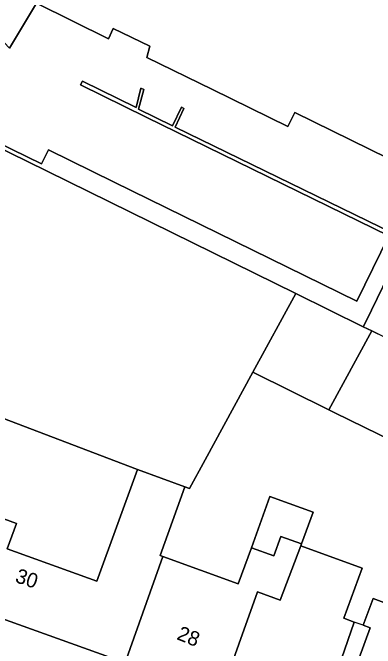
# Model space of a CAD drawing. Extents: x 160023 to 161302, y 384750 to 385707.
# Drawn here: x 160652.2 to 160677, y 385250.71 to 385294.19 of the extents above; entities that cross this region are included whole.
import ezdxf

# ---------------------------------------------------------------- set-up
doc = ezdxf.new("R2010")
doc.units = 0
for name, color, linetype in [('IMGEO_Erf', 7, 'Continuous'), ('IMGEO_Muur', 7, 'Continuous'), ('IMGEO_Pand', 7, 'Continuous'), ('IMGEO_Pand_nummerreeks', 7, 'Continuous'), ('IMGEO_Pand_overbouw', 7, 'Continuous'), ('IMGEO_Voetpad_open', 7, 'Continuous')]:
    doc.layers.add(name, color=color, linetype=linetype)

msp = doc.modelspace()

# ---------------------------------------------------------------- linework, layer by layer
at = {"layer": 'IMGEO_Erf'}
for points in [[(160689.378, 385278.591), (160671.488, 385287.366), (160671.014, 385286.405), (160665.855, 385288.934), (160661.365, 385291.134), (160661.571, 385291.91), (160659.07, 385293.109), (160658.75, 385292.417), (160653.825, 385294.836), (160651.991, 385291.772)], [(160649.069, 385286.341), (160654.173, 385283.853), (160654.654, 385284.802), (160659.144, 385282.6), (160675.733, 385274.462), (160677.927, 385278.94), (160661.328, 385287.057), (160656.836, 385289.253), (160656.984, 385289.518), (160660.638, 385287.701), (160660.971, 385289.036), (160661.179, 385288.947), (160660.815, 385287.596), (160663.133, 385286.456), (160663.734, 385287.727), (160663.915, 385287.639), (160663.312, 385286.373), (160679.084, 385278.668), (160676.343, 385273.047), (160676.178, 385272.71), (160676.768, 385272.42), (160677.177, 385272.22)], [(160680.258, 385263.867), (160674.239, 385266.827), (160673.831, 385267.028), (160668.622, 385269.591), (160665.364, 385263.611), (160664.293, 385261.646), (160663.97, 385261.763), (160662.283, 385257.055), (160662.474, 385256.986), (160667.621, 385255.114), (160668.522, 385257.591), (160669.796, 385261.095), (160671.111, 385260.617), (160672.746, 385260.023), (160671.956, 385257.849), (160671.906, 385257.713), (160676.097, 385256.189), (160674.851, 385252.763), (160675.556, 385252.507), (160674.688, 385250)], [(160675.885, 385250), (160676.645, 385252.112), (160676.169, 385252.285), (160676.853, 385254.114), (160677.592, 385253.837)]]:
    msp.add_lwpolyline(points, dxfattribs=at)
msp.add_lwpolyline([(160660.727, 385262.941), (160650.478, 385266.833), (160649.617, 385264.465), (160650.379, 385264.188), (160649.038, 385260.498), (160652.456, 385259.256), (160651.826, 385257.523), (160657.949, 385255.297)], close=True, dxfattribs=at)
at = {"layer": 'IMGEO_Muur'}
msp.add_lwpolyline([(160679.084, 385278.668), (160663.312, 385286.373), (160663.915, 385287.639), (160663.734, 385287.727), (160663.133, 385286.456), (160660.815, 385287.596), (160661.179, 385288.947), (160660.971, 385289.036), (160660.638, 385287.701), (160656.984, 385289.518), (160656.836, 385289.253), (160661.328, 385287.057), (160677.927, 385278.94), (160675.733, 385274.462), (160659.144, 385282.6), (160654.654, 385284.802), (160654.173, 385283.853), (160649.069, 385286.341), (160648.914, 385286.122), (160653.165, 385284.031), (160671.559, 385274.983), (160676.178, 385272.71), (160676.343, 385273.047)], close=True, dxfattribs=at)
at = {"layer": 'IMGEO_Pand'}
for points in [[(160653.825, 385294.836), (160658.75, 385292.417), (160659.07, 385293.109), (160661.571, 385291.91), (160661.365, 385291.134), (160665.855, 385288.934), (160671.014, 385286.405), (160671.488, 385287.366), (160689.378, 385278.591)], [(160659.974, 385250), (160662.474, 385256.986), (160662.283, 385257.055), (160663.97, 385261.763), (160660.727, 385262.941), (160657.949, 385255.297), (160651.826, 385257.523), (160652.456, 385259.256), (160649.038, 385260.498), (160650.379, 385264.188), (160649.617, 385264.465), (160650.478, 385266.833), (160648.891, 385267.409), (160644.833, 385269.176), (160643.748, 385266.188), (160639.654, 385267.675), (160639.265, 385266.604), (160638.538, 385266.264), (160637.856, 385264.388), (160638.238, 385263.57), (160636.978, 385260.104), (160645.265, 385257.093), (160644.582, 385255.212), (160659.142, 385250)]]:
    msp.add_lwpolyline(points, dxfattribs=at)
for points in [[(160671.559, 385274.983), (160653.165, 385284.031), (160648.914, 385286.122), (160648.678, 385286.238), (160642.926, 385274.57), (160643.169, 385274.482), (160643.026, 385274.089), (160641.66, 385274.22), (160640.663, 385271.476), (160644.833, 385269.176), (160648.891, 385267.409), (160650.478, 385266.833), (160660.727, 385262.941), (160663.97, 385261.763), (160664.293, 385261.646), (160665.364, 385263.611), (160668.622, 385269.591)], [(160676.768, 385272.42), (160676.178, 385272.71), (160671.559, 385274.983), (160668.622, 385269.591), (160673.831, 385267.028)], [(160682.966, 385269.372), (160677.177, 385272.22), (160676.768, 385272.42), (160673.831, 385267.028), (160674.239, 385266.827), (160680.258, 385263.867), (160681.775, 385266.95)], [(160668.522, 385257.591), (160670.061, 385257.04), (160670.533, 385258.359), (160671.956, 385257.849), (160672.746, 385260.023), (160671.111, 385260.617), (160669.796, 385261.095)], [(160668.947, 385254.571), (160670.497, 385254.002), (160671.906, 385257.713), (160671.956, 385257.849), (160670.533, 385258.359), (160670.061, 385257.04), (160668.522, 385257.591), (160667.621, 385255.114), (160662.474, 385256.986), (160659.974, 385250), (160659.879, 385249.736), (160666.383, 385247.408)], [(160675.556, 385252.507), (160674.851, 385252.763), (160676.097, 385256.189), (160671.906, 385257.713), (160670.497, 385254.002), (160668.947, 385254.571), (160666.383, 385247.408), (160672.971, 385245.05), (160674.61, 385249.774), (160674.688, 385250)], [(160683.182, 385249.434), (160681.881, 385250), (160683.086, 385253.559), (160683.224, 385253.966), (160678.326, 385255.798), (160677.592, 385253.837), (160676.853, 385254.114), (160676.169, 385252.285), (160676.645, 385252.112), (160675.885, 385250), (160675.666, 385249.391), (160673.97, 385244.687), (160680.582, 385242.281)]]:
    msp.add_lwpolyline(points, close=True, dxfattribs=at)
at = {"layer": 'IMGEO_Pand_overbouw'}
msp.add_lwpolyline([(160675.556, 385252.507), (160674.688, 385250), (160674.61, 385249.774), (160672.971, 385245.05), (160673.97, 385244.687), (160676.645, 385252.112), (160676.169, 385252.285)], close=True, dxfattribs=at)
at = {"layer": 'IMGEO_Voetpad_open'}
for points in [[(160667.487, 385318.357), (160664.42, 385318.987), (160661.219, 385313.176), (160658.126, 385308.018), (160649.267, 385294.611), (160651.991, 385291.772), (160653.825, 385294.836)], [(160680.582, 385242.281), (160673.97, 385244.687), (160672.971, 385245.05), (160666.383, 385247.408), (160659.879, 385249.736), (160659.142, 385250), (160644.582, 385255.212), (160633.666, 385259.027), (160633.619, 385269.792), (160630.75, 385268.564)]]:
    msp.add_lwpolyline(points, dxfattribs=at)

# ---------------------------------------------------------------- texts
at = {"layer": 'IMGEO_Pand_nummerreeks'}
for s, rotation, p in [('30', 341.2929, (160652.309, 385255.256)), ('28', 337.9812, (160663.36, 385251.348))]:
    msp.add_text(s, height=1, rotation=rotation, dxfattribs=at).set_placement(p)

doc.saveas('drawing.dxf')
